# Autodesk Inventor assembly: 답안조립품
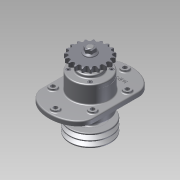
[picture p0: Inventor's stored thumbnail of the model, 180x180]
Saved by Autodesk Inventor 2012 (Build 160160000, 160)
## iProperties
Created: 2015-02
Part Number: 답안조립품
Document SubType Name: Assembly
Designer: Administrator
Author: Administrator
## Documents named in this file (12)
- C:\Documents and Settings\Administrator\바탕 화면\450207V1003\답안조립품.iam
- C:\Documents and Settings\Administrator\바탕 화면\450207V1003\1-본체.ipt
- C:\Documents and Settings\Administrator\바탕 화면\450207V1003\6-베어링 6206.ipt
- C:\Documents and Settings\Administrator\바탕 화면\450207V1003\7-부시.ipt
- C:\Documents and Settings\Administrator\바탕 화면\450207V1003\3-축.ipt
- C:\Documents and Settings\Administrator\바탕 화면\450207V1003\2-커버.ipt
- C:\Documents and Settings\Administrator\바탕 화면\450207V1003\11-키 6x6.ipt
- C:\Documents and Settings\Administrator\바탕 화면\450207V1003\8-오일실 30x42.ipt
- C:\Documents and Settings\Administrator\바탕 화면\450207V1003\10-M6.ipt
- C:\Documents and Settings\Administrator\바탕 화면\450207V1003\4-V벨트풀리.ipt
- C:\Documents and Settings\Administrator\바탕 화면\450207V1003\9-M16-너트.ipt
- C:\Documents and Settings\Administrator\바탕 화면\450207V1003\5-체인 스프로킷.ipt
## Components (23 placed, 11 different names)
1. 1-본체:1
2. 6-베어링 6206:1
3. 7-부시:1
4. 3-축:1
5. 6-베어링 6206:2
6. 2-커버:1
7. 2-커버:2
8. 11-키 6x6:1
9. 11-키 6x6:2
10. 8-8-오일실 30x42:1
11. 8-8-오일실 30x42:2
12. 10-M6:1
13. 10-M6:2
14. 10-M6:3
15. 10-M6:4
16. 10-M6:5
17. 10-M6:6
18. 10-M6:7
19. 10-M6:8
20. 4-V벨트풀리:1
21. 9-M16 너트:1
22. 5-체인 스프로킷:1
23. 9-M16 너트:2
